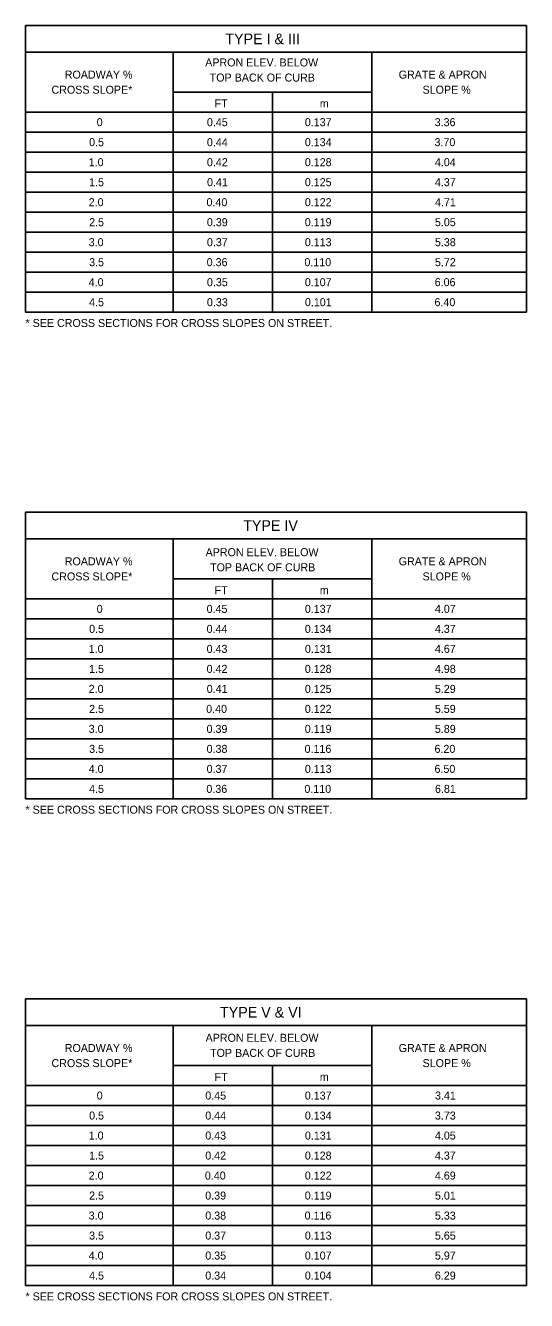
# Model space of a CAD drawing. Extents: x 49991.4 to 50048.3, y 49987.6 to 50018.3.
# Drawn here: x 50034.76 to 50038.52, y 49998.54 to 50008.1 of the extents above; entities that cross this region are included whole.
import ezdxf

# ---------------------------------------------------------------- set-up
doc = ezdxf.new("R2010")
doc.units = 0
doc.layers.add('Level 2', color=7, linetype='Continuous')

msp = doc.modelspace()

# ---------------------------------------------------------------- linework, layer by layer
at = {"layer": 'Level 2'}
for p, q in [((50034.7616, 50008.104), (50038.5197, 50008.104)), ((50034.7616, 50005.954), (50034.7616, 50008.104)), ((50038.5197, 50008.104), (50038.5197, 50005.954)), ((50034.7616, 50007.904), (50038.5197, 50007.904)), ((50035.8701, 50005.954), (50035.8701, 50007.904)), ((50037.3596, 50007.904), (50037.3596, 50005.954)), ((50035.8701, 50007.604), (50037.3596, 50007.604)), ((50036.6148, 50007.604), (50036.6148, 50005.954)), ((50034.7616, 50007.454), (50038.5197, 50007.454)), ((50034.7616, 50007.304), (50038.5197, 50007.304)), ((50034.7616, 50007.154), (50038.5197, 50007.154)), ((50034.7616, 50007.004), (50038.5197, 50007.004)), ((50034.7616, 50006.854), (50038.5197, 50006.854)), ((50034.7616, 50006.704), (50038.5197, 50006.704)), ((50034.7616, 50006.554), (50038.5197, 50006.554)), ((50034.7616, 50006.404), (50038.5197, 50006.404)), ((50034.7616, 50006.254), (50038.5197, 50006.254)), ((50034.7616, 50006.104), (50038.5197, 50006.104)), ((50034.7616, 50005.954), (50038.5197, 50005.954)), ((50034.7616, 50004.454), (50038.5197, 50004.454)), ((50034.7616, 50002.304), (50034.7616, 50004.454)), ((50038.5197, 50004.454), (50038.5197, 50002.304)), ((50034.7616, 50004.254), (50038.5197, 50004.254)), ((50035.8701, 50002.304), (50035.8701, 50004.254)), ((50037.3596, 50004.254), (50037.3596, 50002.304)), ((50035.8701, 50003.954), (50037.3596, 50003.954)), ((50036.6148, 50003.954), (50036.6148, 50002.304)), ((50034.7616, 50003.804), (50038.5197, 50003.804)), ((50034.7616, 50003.654), (50038.5197, 50003.654)), ((50034.7616, 50003.504), (50038.5197, 50003.504)), ((50034.7616, 50003.354), (50038.5197, 50003.354)), ((50034.7616, 50003.204), (50038.5197, 50003.204)), ((50034.7616, 50003.054), (50038.5197, 50003.054)), ((50034.7616, 50002.904), (50038.5197, 50002.904)), ((50034.7616, 50002.754), (50038.5197, 50002.754)), ((50034.7616, 50002.604), (50038.5197, 50002.604)), ((50034.7616, 50002.454), (50038.5197, 50002.454)), ((50034.7616, 50002.304), (50038.5197, 50002.304)), ((50034.7616, 50000.804), (50038.5197, 50000.804)), ((50034.7616, 49998.654), (50034.7616, 50000.804)), ((50038.5197, 50000.804), (50038.5197, 49998.654)), ((50034.7616, 50000.604), (50038.5197, 50000.604)), ((50035.8701, 49998.654), (50035.8701, 50000.604)), ((50037.3596, 50000.604), (50037.3596, 49998.654)), ((50035.8701, 50000.304), (50037.3596, 50000.304)), ((50036.6148, 50000.304), (50036.6148, 49998.654)), ((50034.7616, 50000.154), (50038.5197, 50000.154)), ((50034.7616, 50000.004), (50038.5197, 50000.004)), ((50034.7616, 49999.854), (50038.5197, 49999.854)), ((50034.7616, 49999.704), (50038.5197, 49999.704)), ((50034.7616, 49999.554), (50038.5197, 49999.554)), ((50034.7616, 49999.404), (50038.5197, 49999.404)), ((50034.7616, 49999.254), (50038.5197, 49999.254)), ((50034.7616, 49999.104), (50038.5197, 49999.104)), ((50034.7616, 49998.954), (50038.5197, 49998.954)), ((50034.7616, 49998.804), (50038.5197, 49998.804)), ((50034.7616, 49998.654), (50038.5197, 49998.654))]:
    msp.add_line(p, q, dxfattribs=at)

# ---------------------------------------------------------------- texts
for s, height, p in [('TYPE I & III', 0.08, (50036.2607, 50007.9639)), ('APRON ELEV. BELOW', 0.06, (50036.1098, 50007.7969)), ('ROADWAY %', 0.06, (50035.0562, 50007.7056)), ('TOP BACK OF CURB', 0.06, (50036.1433, 50007.6835)), ('GRATE & APRON', 0.06, (50037.561, 50007.7056)), ('CROSS SLOPE*', 0.06, (50034.9566, 50007.5923)), ('SLOPE %', 0.06, (50037.74, 50007.5923)), ('FT', 0.06, (50036.1799, 50007.4891)), ('m', 0.06, (50036.9692, 50007.4891)), ('0', 0.06, (50035.2958, 50007.349)), ('0.45', 0.06, (50036.1225, 50007.349)), ('0.137', 0.06, (50036.8568, 50007.349)), ('3.36', 0.06, (50037.831, 50007.349)), ('0.5', 0.06, (50035.2389, 50007.199)), ('0.44', 0.06, (50036.1225, 50007.199)), ('0.134', 0.06, (50036.8568, 50007.199)), ('3.70', 0.06, (50037.8296, 50007.199)), ('1.0', 0.06, (50035.2358, 50007.049)), ('0.42', 0.06, (50036.1225, 50007.049)), ('0.128', 0.06, (50036.8568, 50007.049)), ('4.04', 0.06, (50037.8326, 50007.049)), ('1.5', 0.06, (50035.2389, 50006.899)), ('0.41', 0.06, (50036.1231, 50006.899)), ('0.125', 0.06, (50036.8568, 50006.899)), ('4.37', 0.06, (50037.8326, 50006.899)), ('2.0', 0.06, (50035.2358, 50006.749)), ('0.40', 0.06, (50036.1194, 50006.749)), ('0.122', 0.06, (50036.8568, 50006.749)), ('4.71', 0.06, (50037.8332, 50006.749)), ('2.5', 0.06, (50035.2389, 50006.599)), ('0.39', 0.06, (50036.1223, 50006.599)), ('0.119', 0.06, (50036.8565, 50006.599)), ('5.05', 0.06, (50037.8326, 50006.599)), ('3.0', 0.06, (50035.2358, 50006.449)), ('0.37', 0.06, (50036.1225, 50006.449)), ('0.113', 0.06, (50036.8568, 50006.449)), ('5.38', 0.06, (50037.8326, 50006.449)), ('3.5', 0.06, (50035.2389, 50006.299)), ('0.36', 0.06, (50036.1209, 50006.299)), ('0.110', 0.06, (50036.8537, 50006.299)), ('5.72', 0.06, (50037.8326, 50006.299)), ('4.0', 0.06, (50035.2358, 50006.149)), ('0.35', 0.06, (50036.1225, 50006.149)), ('0.107', 0.06, (50036.8568, 50006.149)), ('6.06', 0.06, (50037.831, 50006.149)), ('4.5', 0.06, (50035.2389, 50005.999)), ('0.33', 0.06, (50036.1225, 50005.999)), ('0.101', 0.06, (50036.8574, 50005.999)), ('6.40', 0.06, (50037.8296, 50005.999)), ('* SEE CROSS SECTIONS FOR CROSS SLOPES ON STREET.', 0.06, (50034.7616, 50005.8428)), ('TYPE IV', 0.08, (50036.3945, 50004.3139)), ('APRON ELEV. BELOW', 0.06, (50036.1126, 50004.1241)), ('ROADWAY %', 0.06, (50035.0562, 50004.0556)), ('GRATE & APRON', 0.06, (50037.561, 50004.0556)), ('CROSS SLOPE*', 0.06, (50034.9566, 50003.9423)), ('TOP BACK OF CURB', 0.06, (50036.1462, 50004.0107)), ('SLOPE %', 0.06, (50037.74, 50003.9423)), ('FT', 0.06, (50036.1799, 50003.8391)), ('m', 0.06, (50036.9692, 50003.8391)), ('0', 0.06, (50035.2958, 50003.699)), ('0.45', 0.06, (50036.1202, 50003.699)), ('0.137', 0.06, (50036.8568, 50003.699)), ('4.07', 0.06, (50037.8326, 50003.699)), ('0.5', 0.06, (50035.2389, 50003.549)), ('0.44', 0.06, (50036.1202, 50003.549)), ('0.134', 0.06, (50036.8568, 50003.549)), ('4.37', 0.06, (50037.8326, 50003.549)), ('1.0', 0.06, (50035.2358, 50003.399)), ('0.43', 0.06, (50036.1202, 50003.399)), ('0.131', 0.06, (50036.8574, 50003.399)), ('4.67', 0.06, (50037.8326, 50003.399)), ('1.5', 0.06, (50035.2389, 50003.249)), ('0.42', 0.06, (50036.1202, 50003.249)), ('0.128', 0.06, (50036.8568, 50003.249)), ('4.98', 0.06, (50037.8326, 50003.249)), ('2.0', 0.06, (50035.2358, 50003.099)), ('0.41', 0.06, (50036.1208, 50003.099)), ('0.125', 0.06, (50036.8568, 50003.099)), ('5.29', 0.06, (50037.8324, 50003.099)), ('2.5', 0.06, (50035.2389, 50002.949)), ('0.40', 0.06, (50036.1171, 50002.949)), ('0.122', 0.06, (50036.8568, 50002.949)), ('5.59', 0.06, (50037.8324, 50002.949)), ('3.0', 0.06, (50035.2358, 50002.799)), ('0.39', 0.06, (50036.12, 50002.799)), ('0.119', 0.06, (50036.8565, 50002.799)), ('5.89', 0.06, (50037.8324, 50002.799)), ('3.5', 0.06, (50035.2389, 50002.649)), ('0.38', 0.06, (50036.1202, 50002.649)), ('0.116', 0.06, (50036.8551, 50002.649)), ('6.20', 0.06, (50037.8296, 50002.649)), ('4.0', 0.06, (50035.2358, 50002.499)), ('0.37', 0.06, (50036.1202, 50002.499)), ('0.113', 0.06, (50036.8568, 50002.499)), ('6.50', 0.06, (50037.8296, 50002.499)), ('4.5', 0.06, (50035.2389, 50002.349)), ('0.36', 0.06, (50036.1185, 50002.349)), ('0.110', 0.06, (50036.8537, 50002.349)), ('6.81', 0.06, (50037.8332, 50002.349)), ('* SEE CROSS SECTIONS FOR CROSS SLOPES ON STREET.', 0.06, (50034.7616, 50002.1928)), ('TYPE V & VI', 0.08, (50036.2207, 50000.6639)), ('ROADWAY %', 0.06, (50035.0562, 50000.4056)), ('APRON ELEV. BELOW', 0.06, (50036.1126, 50000.4822)), ('GRATE & APRON', 0.06, (50037.561, 50000.4056)), ('TOP BACK OF CURB', 0.06, (50036.1462, 50000.3689)), ('CROSS SLOPE*', 0.06, (50034.9566, 50000.2923)), ('SLOPE %', 0.06, (50037.74, 50000.2923)), ('FT', 0.06, (50036.1799, 50000.1891)), ('m', 0.06, (50036.9692, 50000.1891)), ('0', 0.06, (50035.2958, 50000.049)), ('0.45', 0.06, (50036.1102, 50000.049)), ('0.137', 0.06, (50036.8568, 50000.049)), ('3.41', 0.06, (50037.8332, 50000.049)), ('0.5', 0.06, (50035.2389, 49999.899)), ('0.44', 0.06, (50036.1102, 49999.899)), ('0.134', 0.06, (50036.8568, 49999.899)), ('3.73', 0.06, (50037.8326, 49999.899)), ('1.0', 0.06, (50035.2358, 49999.749)), ('0.43', 0.06, (50036.1102, 49999.749)), ('0.131', 0.06, (50036.8574, 49999.749)), ('4.05', 0.06, (50037.8326, 49999.749)), ('1.5', 0.06, (50035.2389, 49999.599)), ('0.42', 0.06, (50036.1102, 49999.599)), ('0.128', 0.06, (50036.8568, 49999.599)), ('4.37', 0.06, (50037.8326, 49999.599)), ('2.0', 0.06, (50035.2358, 49999.449)), ('0.40', 0.06, (50036.1071, 49999.449)), ('0.122', 0.06, (50036.8568, 49999.449)), ('4.69', 0.06, (50037.8324, 49999.449)), ('2.5', 0.06, (50035.2389, 49999.299)), ('0.39', 0.06, (50036.1099, 49999.299)), ('0.119', 0.06, (50036.8565, 49999.299)), ('5.01', 0.06, (50037.8332, 49999.299)), ('3.0', 0.06, (50035.2358, 49999.149)), ('0.38', 0.06, (50036.1102, 49999.149)), ('0.116', 0.06, (50036.8551, 49999.149)), ('5.33', 0.06, (50037.8326, 49999.149)), ('3.5', 0.06, (50035.2389, 49998.999)), ('0.37', 0.06, (50036.1102, 49998.999)), ('0.113', 0.06, (50036.8568, 49998.999)), ('5.65', 0.06, (50037.8326, 49998.999)), ('4.0', 0.06, (50035.2358, 49998.849)), ('0.35', 0.06, (50036.1102, 49998.849)), ('0.107', 0.06, (50036.8568, 49998.849)), ('5.97', 0.06, (50037.8326, 49998.849)), ('4.5', 0.06, (50035.2389, 49998.699)), ('0.34', 0.06, (50036.1102, 49998.699)), ('0.104', 0.06, (50036.8568, 49998.699)), ('6.29', 0.06, (50037.8324, 49998.699)), ('* SEE CROSS SECTIONS FOR CROSS SLOPES ON STREET.', 0.06, (50034.7616, 49998.5428))]:
    msp.add_text(s, height=height, dxfattribs=at).set_placement(p)

doc.saveas('drawing.dxf')
